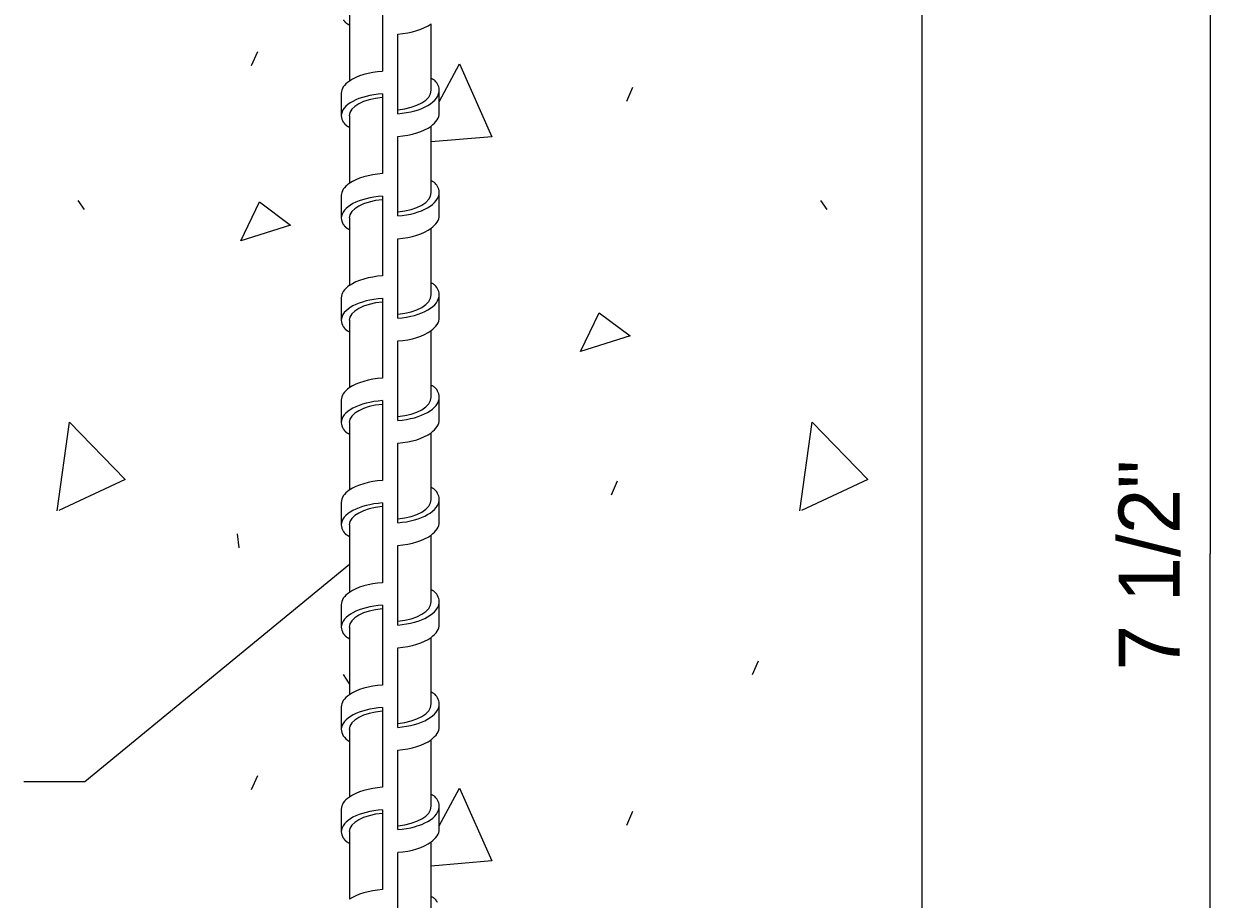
# Model space of a CAD drawing. Extents: x 99988 to 100172, y 99995 to 100047.
# Drawn here: x 100013.574 to 100014.934, y 100005.845 to 100006.848 of the extents above; entities that cross this region are included whole.
import ezdxf

# ---------------------------------------------------------------- set-up
doc = ezdxf.new("R2010")
doc.units = 0
for name, color, linetype in [('Level 10', 7, 'Continuous'), ('Level 15', 7, 'Continuous'), ('Level 2', 7, 'Continuous'), ('Level 20', 7, 'Continuous'), ('Level 3', 7, 'Continuous')]:
    doc.layers.add(name, color=color, linetype=linetype)

msp = doc.modelspace()

# ---------------------------------------------------------------- linework, layer by layer
at = {"layer": 'Level 10'}
for p, q in [((100013.9475, 100006.8595), (100013.9475, 100006.8463)), ((100013.9475, 100006.8463), (100013.9475, 100006.782)), ((100014.0412, 100006.7851), (100014.0412, 100006.8477)), ((100014.0412, 100006.7714), (100014.0412, 100006.7851)), ((100013.9382, 100006.768), (100013.9382, 100006.7423)), ((100014.0505, 100006.7454), (100014.0505, 100006.7714)), ((100013.9475, 100006.7423), (100013.9475, 100006.7292)), ((100013.9475, 100006.7291), (100013.9475, 100006.6648)), ((100014.0412, 100006.6679), (100014.0412, 100006.7305)), ((100014.0412, 100006.6543), (100014.0412, 100006.6679)), ((100014.0505, 100006.6282), (100014.0505, 100006.6543)), ((100013.9382, 100006.6508), (100013.9382, 100006.6251)), ((100013.9475, 100006.6251), (100013.9475, 100006.6119)), ((100014.0412, 100006.5507), (100014.0412, 100006.6133)), ((100013.9475, 100006.6119), (100013.9475, 100006.5477)), ((100014.0412, 100006.5371), (100014.0412, 100006.5507)), ((100013.9382, 100006.5337), (100013.9382, 100006.5079)), ((100014.0505, 100006.511), (100014.0505, 100006.5371)), ((100013.9475, 100006.5079), (100013.9475, 100006.4948)), ((100013.9475, 100006.4948), (100013.9475, 100006.4305)), ((100014.0412, 100006.4335), (100014.0412, 100006.4961)), ((100014.0412, 100006.4199), (100014.0412, 100006.4335)), ((100013.9382, 100006.4165), (100013.9382, 100006.3907)), ((100014.0505, 100006.3939), (100014.0505, 100006.4199)), ((100013.9475, 100006.3907), (100013.9475, 100006.3773)), ((100013.9475, 100006.3773), (100013.9475, 100006.3133)), ((100014.0412, 100006.3163), (100014.0412, 100006.3789)), ((100014.0412, 100006.3027), (100014.0412, 100006.3163)), ((100014.0505, 100006.2767), (100014.0505, 100006.303)), ((100013.9382, 100006.2993), (100013.9382, 100006.2735)), ((100013.9475, 100006.2735), (100013.9475, 100006.2603)), ((100013.9475, 100006.2603), (100013.9475, 100006.1961)), ((100014.0412, 100006.1991), (100014.0412, 100006.2617)), ((100013.9475, 100006.1961), (100013.9475, 100006.1961)), ((100014.0412, 100006.1855), (100014.0412, 100006.1991)), ((100013.9382, 100006.1821), (100013.9382, 100006.1564)), ((100014.0505, 100006.1595), (100014.0505, 100006.1855)), ((100013.9475, 100006.1564), (100013.9475, 100006.1432)), ((100013.9475, 100006.1432), (100013.9475, 100006.0789)), ((100014.0412, 100006.0819), (100014.0412, 100006.1446)), ((100014.0412, 100006.0683), (100014.0412, 100006.0819)), ((100013.9382, 100006.0649), (100013.9382, 100006.0392)), ((100014.0505, 100006.0423), (100014.0505, 100006.0683)), ((100013.9475, 100006.0392), (100013.9475, 100006.0251)), ((100013.9475, 100006.0251), (100013.9475, 100005.9617)), ((100014.0412, 100005.9648), (100014.0412, 100006.0274)), ((100014.0412, 100005.9511), (100014.0412, 100005.9648)), ((100013.9382, 100005.9477), (100013.9382, 100005.922)), ((100014.0505, 100005.9251), (100014.0505, 100005.9511)), ((100013.9475, 100005.922), (100013.9475, 100005.9087)), ((100013.9475, 100005.9087), (100013.9475, 100005.8445)), ((100014.0412, 100005.8476), (100014.0412, 100005.9102)), ((100014.0412, 100005.8339), (100014.0412, 100005.8476))]:
    msp.add_line(p, q, dxfattribs=at)
for centre, major_axis, ratio, start_param, end_param in [((100013.9943, 100006.8626), (-0.0561, 0), 0.483341, 1.726906, 2.559242), ((100013.9943, 100006.768), (-0.0561, 0), 0.453331, 4.868499, 5.700713), ((100013.9943, 100006.768), (-0.0561, 0), 0.453331, 5.700747, 6.28324), ((100013.9943, 100006.7714), (-0.0561, 0), 0.483341, 3.170728, 3.398624), ((100013.9943, 100006.7423), (-0.0561, 0), 0.453331, 4.868499, 6.291084), ((100013.9943, 100006.7423), (-0.0469, 0), 0.453331, 4.899667, 6.283186), ((100013.9943, 100006.7714), (-0.0561, 0), 0.483341, 1.726906, 3.170728), ((100013.9943, 100006.7714), (0.0469, 0), 0.483341, 4.899667, 6.283186), ((100013.9943, 100006.7423), (-0.0561, 0), 0.453331, 0.007899, 0.291099), ((100013.9943, 100006.7454), (-0.0561, 0), 0.483341, 2.559062, 3.141593), ((100013.9943, 100006.7454), (-0.0561, 0), 0.483341, 1.726906, 2.559062), ((100013.9943, 100006.6508), (-0.0561, 0), 0.453331, 4.868499, 5.701215), ((100013.9943, 100006.6508), (-0.0561, 0), 0.453331, 5.701416, 6.28324), ((100013.9943, 100006.6543), (-0.0561, 0), 0.483341, 1.726906, 3.154379), ((100013.9943, 100006.6543), (0.0469, 0), 0.483341, 4.899667, 6.283186), ((100013.9943, 100006.6543), (-0.0561, 0), 0.483341, 3.157463, 3.398624), ((100013.9943, 100006.6543), (-0.0561, 0), 0.483341, 3.1559612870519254, 3.1559613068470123), ((100013.9943, 100006.6251), (-0.0561, 0), 0.453331, 4.868499, 6.285718), ((100013.9943, 100006.6251), (-0.0469, 0), 0.453331, 4.899667, 6.283186), ((100013.9943, 100006.6282), (-0.0561, 0), 0.483341, 2.559277, 3.141593), ((100013.9943, 100006.6251), (-0.0561, 0), 0.453331, 0.002533, 0.291099), ((100013.9943, 100006.6282), (-0.0561, 0), 0.483341, 1.726906, 2.559239), ((100013.9943, 100006.5337), (-0.0561, 0), 0.453331, 5.700807, 6.28324), ((100013.9943, 100006.5337), (-0.0561, 0), 0.453331, 4.868499, 5.700732), ((100013.9943, 100006.5079), (-0.0561, 0), 0.453331, 4.868499, 6.286829), ((100013.9943, 100006.5371), (-0.0561, 0), 0.483341, 1.726906, 3.164039), ((100013.9943, 100006.5371), (0.0469, 0), 0.483341, 4.899667, 6.283186), ((100013.9943, 100006.5371), (-0.0561, 0), 0.483341, 3.164109, 3.398624), ((100013.9943, 100006.5079), (-0.0469, 0), 0.453331, 4.899667, 6.283186), ((100013.9943, 100006.5079), (-0.0561, 0), 0.453331, 0.003942, 0.291099), ((100013.9943, 100006.511), (-0.0561, 0), 0.483341, 2.559128, 3.141593), ((100013.9943, 100006.511), (-0.0561, 0), 0.483341, 1.726906, 2.55906), ((100013.9943, 100006.4165), (-0.0561, 0), 0.453331, 4.868499, 5.70104), ((100013.9943, 100006.4165), (-0.0561, 0), 0.453331, 5.70104, 6.28324), ((100013.9943, 100006.4199), (-0.0561, 0), 0.483341, 3.148125, 3.398624), ((100013.9943, 100006.3907), (-0.0561, 0), 0.453331, 4.868499, 6.287652), ((100013.9943, 100006.3907), (-0.0469, 0), 0.453331, 4.899667, 6.283186), ((100013.9943, 100006.4199), (-0.0561, 0), 0.483341, 1.726906, 3.145553), ((100013.9943, 100006.4199), (0.0469, 0), 0.483341, 4.899667, 6.283186), ((100013.9943, 100006.4199), (-0.0561, 0), 0.483341, 3.14727, 3.148125), ((100013.9943, 100006.3907), (-0.0561, 0), 0.453331, 0.004522, 0.291099), ((100013.9943, 100006.3939), (-0.0561, 0), 0.483341, 2.559329, 3.141593), ((100013.9943, 100006.3939), (-0.0561, 0), 0.483341, 1.726906, 2.559329), ((100013.9943, 100006.2993), (-0.0561, 0), 0.453331, 4.868499, 5.700838), ((100013.9943, 100006.2993), (-0.0561, 0), 0.453331, 5.700838, 6.28324), ((100013.9943, 100006.3027), (-0.0561, 0), 0.483341, 1.726906, 3.154112), ((100013.9943, 100006.3027), (0.0469, 0), 0.483341, 4.899667, 6.283186), ((100013.9943, 100006.3027), (-0.0561, 0), 0.483341, 3.154112, 3.398624), ((100013.9943, 100006.2735), (-0.0561, 0), 0.453331, 4.868499, 6.287148), ((100013.9943, 100006.2735), (-0.0469, 0), 0.453331, 4.899667, 6.283186), ((100013.9943, 100006.2735), (-0.0561, 0), 0.453331, 0.003963, 0.291099), ((100013.9943, 100006.2767), (-0.0561, 0), 0.483341, 2.559264, 3.141593), ((100013.9943, 100006.2767), (-0.0561, 0), 0.483341, 1.726906, 2.559243), ((100013.9943, 100006.1821), (-0.0561, 0), 0.453331, 4.868499, 5.699987), ((100013.9943, 100006.1821), (-0.0561, 0), 0.453331, 5.699987, 6.28324), ((100013.9943, 100006.1855), (-0.0561, 0), 0.483341, 3.156067, 3.398624), ((100013.9943, 100006.1564), (-0.0561, 0), 0.453331, 4.868499, 6.285215), ((100013.9943, 100006.1855), (-0.0561, 0), 0.483341, 1.726906, 3.154373), ((100013.9943, 100006.1855), (0.0469, 0), 0.483341, 4.899667, 6.283186), ((100013.9943, 100006.1855), (-0.0561, 0), 0.483341, 3.155233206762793, 3.1552332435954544), ((100013.9943, 100006.1564), (-0.0469, 0), 0.453331, 4.899667, 6.283186), ((100013.9943, 100006.1564), (-0.0561, 0), 0.453331, 0.002031, 0.291099), ((100013.9943, 100006.1595), (-0.0561, 0), 0.483341, 2.559645, 3.141593), ((100013.9943, 100006.1595), (-0.0561, 0), 0.483341, 1.726906, 2.559645), ((100013.9943, 100006.0649), (-0.0561, 0), 0.453331, 4.868499, 5.700435), ((100013.9943, 100006.0649), (-0.0561, 0), 0.453331, 5.700435, 6.28324), ((100013.9943, 100006.0683), (-0.0561, 0), 0.483341, 3.15176, 3.398624), ((100013.9943, 100006.0392), (-0.0561, 0), 0.453331, 4.868499, 6.279323), ((100013.9943, 100006.0392), (-0.0469, 0), 0.453331, 4.899667, 6.283186), ((100013.9943, 100006.0683), (-0.0561, 0), 0.483341, 1.726906, 3.15176), ((100013.9943, 100006.0683), (0.0469, 0), 0.483341, 4.899667, 6.283186), ((100013.9943, 100006.0392), (-0.0561, 0), 0.453331, 6.279328, 6.86573), ((100013.9943, 100006.0423), (-0.0561, 0), 0.483341, 2.559545, 3.141593), ((100013.9943, 100006.0423), (-0.0561, 0), 0.483341, 1.726906, 2.559545), ((100013.9943, 100005.9477), (-0.0561, 0), 0.453331, 5.700036, 6.28324), ((100013.9943, 100005.9477), (-0.0561, 0), 0.453331, 4.868499, 5.700036), ((100013.9943, 100005.9511), (-0.0561, 0), 0.483341, 1.726906, 3.163128), ((100013.9943, 100005.9511), (0.0469, 0), 0.483341, 4.899667, 6.283186), ((100013.9943, 100005.9511), (-0.0561, 0), 0.483341, 3.166399, 3.398624), ((100013.9943, 100005.922), (-0.0561, 0), 0.453331, 4.868499, 6.28541), ((100013.9943, 100005.922), (-0.0469, 0), 0.453331, 4.899667, 6.283186), ((100013.9943, 100005.922), (-0.0561, 0), 0.453331, 0.002225, 0.291099), ((100013.9943, 100005.9251), (-0.0561, 0), 0.483341, 2.558021, 3.141593), ((100013.9943, 100005.9251), (-0.0561, 0), 0.483341, 1.726906, 2.55759), ((100013.9943, 100005.8305), (-0.0561, 0), 0.453331, 4.868499, 5.700533)]:
    msp.add_ellipse(centre, major_axis=major_axis, ratio=ratio, start_param=start_param, end_param=end_param, dxfattribs=at)
for points, degree in [([(100013.9856, 100006.8846), (100013.9856, 100006.8817), (100013.9856, 100006.8788), (100013.9856, 100006.876), (100013.9856, 100006.8635), (100013.9856, 100006.851), (100013.9856, 100006.8385), (100013.9856, 100006.8234), (100013.9856, 100006.8083), (100013.9856, 100006.7932)], 3), ([(100013.9406, 100006.8522), (100013.9421, 100006.8499), (100013.9444, 100006.8479), (100013.9475, 100006.8463)], 2), ([(100014.0031, 100006.7446), (100014.0031, 100006.7475), (100014.0031, 100006.7504), (100014.0031, 100006.7533), (100014.0031, 100006.7658), (100014.0031, 100006.7783), (100014.0031, 100006.7908), (100014.0031, 100006.8058), (100014.0031, 100006.8208), (100014.0031, 100006.8358)], 3), ([(100014.0486, 100006.7783), (100014.0472, 100006.7809), (100014.0451, 100006.7831), (100014.0418, 100006.7848), (100014.0415, 100006.7849), (100014.0412, 100006.785)], 3), ([(100013.9856, 100006.7674), (100013.9856, 100006.7645), (100013.9856, 100006.7617), (100013.9856, 100006.7588), (100013.9856, 100006.7463), (100013.9856, 100006.7338), (100013.9856, 100006.7213), (100013.9856, 100006.7062), (100013.9856, 100006.6911), (100013.9856, 100006.676)], 3), ([(100013.9406, 100006.735), (100013.9421, 100006.7327), (100013.9444, 100006.7307), (100013.9475, 100006.7292)], 2), ([(100014.0031, 100006.6275), (100014.0031, 100006.6303), (100014.0031, 100006.6332), (100014.0031, 100006.6361), (100014.0031, 100006.6486), (100014.0031, 100006.6611), (100014.0031, 100006.6736), (100014.0031, 100006.6886), (100014.0031, 100006.7036), (100014.0031, 100006.7186)], 3), ([(100014.0486, 100006.6612), (100014.0472, 100006.6637), (100014.0451, 100006.6659), (100014.0418, 100006.6676), (100014.0415, 100006.6677), (100014.0412, 100006.6679)], 3), ([(100013.9856, 100006.6502), (100013.9856, 100006.6474), (100013.9856, 100006.6445), (100013.9856, 100006.6416), (100013.9856, 100006.6291), (100013.9856, 100006.6166), (100013.9856, 100006.6041), (100013.9856, 100006.589), (100013.9856, 100006.5739), (100013.9856, 100006.5588)], 3), ([(100013.9406, 100006.6178), (100013.9421, 100006.6155), (100013.9444, 100006.6135), (100013.9475, 100006.612)], 2), ([(100014.0031, 100006.5103), (100014.0031, 100006.5132), (100014.0031, 100006.516), (100014.0031, 100006.5189), (100014.0031, 100006.5314), (100014.0031, 100006.5439), (100014.0031, 100006.5564), (100014.0031, 100006.5714), (100014.0031, 100006.5864), (100014.0031, 100006.6014)], 3), ([(100014.0486, 100006.544), (100014.0472, 100006.5465), (100014.0451, 100006.5487), (100014.0418, 100006.5504), (100014.0415, 100006.5505), (100014.0412, 100006.5507)], 3), ([(100013.9856, 100006.5331), (100013.9856, 100006.5302), (100013.9856, 100006.5273), (100013.9856, 100006.5244), (100013.9856, 100006.5119), (100013.9856, 100006.4994), (100013.9856, 100006.4869), (100013.9856, 100006.4718), (100013.9856, 100006.4567), (100013.9856, 100006.4416)], 3), ([(100013.9406, 100006.5006), (100013.9421, 100006.4983), (100013.9444, 100006.4963), (100013.9475, 100006.4948)], 2), ([(100014.0031, 100006.3931), (100014.0031, 100006.396), (100014.0031, 100006.3989), (100014.0031, 100006.4017), (100014.0031, 100006.4142), (100014.0031, 100006.4267), (100014.0031, 100006.4392), (100014.0031, 100006.4542), (100014.0031, 100006.4692), (100014.0031, 100006.4842)], 3), ([(100014.0486, 100006.4268), (100014.0472, 100006.4293), (100014.0451, 100006.4315), (100014.0418, 100006.4332), (100014.0415, 100006.4334), (100014.0412, 100006.4335)], 3), ([(100013.9856, 100006.4159), (100013.9856, 100006.413), (100013.9856, 100006.4101), (100013.9856, 100006.4072), (100013.9856, 100006.3947), (100013.9856, 100006.3822), (100013.9856, 100006.3697), (100013.9856, 100006.3546), (100013.9856, 100006.3395), (100013.9856, 100006.3244)], 3), ([(100013.9406, 100006.3834), (100013.9421, 100006.3811), (100013.9444, 100006.3791), (100013.9475, 100006.3776)], 2), ([(100014.0031, 100006.2759), (100014.0031, 100006.2788), (100014.0031, 100006.2817), (100014.0031, 100006.2845), (100014.0031, 100006.297), (100014.0031, 100006.3095), (100014.0031, 100006.322), (100014.0031, 100006.337), (100014.0031, 100006.3521), (100014.0031, 100006.3671)], 3), ([(100014.0486, 100006.3096), (100014.0472, 100006.3121), (100014.0451, 100006.3143), (100014.0418, 100006.316), (100014.0415, 100006.3162), (100014.0412, 100006.3163)], 3), ([(100013.9856, 100006.2987), (100013.9856, 100006.2958), (100013.9856, 100006.2929), (100013.9856, 100006.29), (100013.9856, 100006.2775), (100013.9856, 100006.265), (100013.9856, 100006.2525), (100013.9856, 100006.2374), (100013.9856, 100006.2223), (100013.9856, 100006.2072)], 3), ([(100013.9406, 100006.2662), (100013.9421, 100006.2639), (100013.9444, 100006.2619), (100013.9475, 100006.2604)], 2), ([(100014.0031, 100006.1587), (100014.0031, 100006.1616), (100014.0031, 100006.1645), (100014.0031, 100006.1674), (100014.0031, 100006.1799), (100014.0031, 100006.1924), (100014.0031, 100006.2049), (100014.0031, 100006.2199), (100014.0031, 100006.2349), (100014.0031, 100006.2499)], 3), ([(100014.0486, 100006.1924), (100014.0472, 100006.1949), (100014.0451, 100006.1971), (100014.0418, 100006.1988), (100014.0415, 100006.199), (100014.0412, 100006.1991)], 3), ([(100013.9856, 100006.1815), (100013.9856, 100006.1786), (100013.9856, 100006.1757), (100013.9856, 100006.1728), (100013.9856, 100006.1603), (100013.9856, 100006.1478), (100013.9856, 100006.1353), (100013.9856, 100006.1202), (100013.9856, 100006.1051), (100013.9856, 100006.09)], 3), ([(100013.9406, 100006.1491), (100013.9421, 100006.1468), (100013.9444, 100006.1448), (100013.9475, 100006.1432)], 2), ([(100014.0031, 100006.0415), (100014.0031, 100006.0444), (100014.0031, 100006.0473), (100014.0031, 100006.0502), (100014.0031, 100006.0627), (100014.0031, 100006.0752), (100014.0031, 100006.0877), (100014.0031, 100006.1027), (100014.0031, 100006.1177), (100014.0031, 100006.1327)], 3), ([(100014.0486, 100006.0752), (100014.0472, 100006.0778), (100014.0451, 100006.0799), (100014.0418, 100006.0817), (100014.0415, 100006.0818), (100014.0412, 100006.0819)], 3), ([(100013.9856, 100006.0643), (100013.9856, 100006.0614), (100013.9856, 100006.0585), (100013.9856, 100006.0556), (100013.9856, 100006.0431), (100013.9856, 100006.0306), (100013.9856, 100006.0181), (100013.9856, 100006.003), (100013.9856, 100005.9879), (100013.9856, 100005.9729)], 3), ([(100014.0031, 100005.9243), (100014.0031, 100005.9272), (100014.0031, 100005.9301), (100014.0031, 100005.933), (100014.0031, 100005.9455), (100014.0031, 100005.958), (100014.0031, 100005.9705), (100014.0031, 100005.9855), (100014.0031, 100006.0005), (100014.0031, 100006.0155)], 3), ([(100014.0486, 100005.958), (100014.0472, 100005.9606), (100014.0451, 100005.9627), (100014.0418, 100005.9645), (100014.0415, 100005.9646), (100014.0412, 100005.9647)], 3), ([(100013.9856, 100005.9471), (100013.9856, 100005.9442), (100013.9856, 100005.9413), (100013.9856, 100005.9385), (100013.9856, 100005.926), (100013.9856, 100005.9135), (100013.9856, 100005.901), (100013.9856, 100005.8859), (100013.9856, 100005.8708), (100013.9856, 100005.8557)], 3), ([(100013.9406, 100005.9147), (100013.9421, 100005.9124), (100013.9444, 100005.9104), (100013.9475, 100005.9088)], 2), ([(100014.0031, 100005.8071), (100014.0031, 100005.81), (100014.0031, 100005.8129), (100014.0031, 100005.8158), (100014.0031, 100005.8283), (100014.0031, 100005.8408), (100014.0031, 100005.8533), (100014.0031, 100005.8683), (100014.0031, 100005.8833), (100014.0031, 100005.8983)], 3), ([(100014.0486, 100005.8408), (100014.0472, 100005.8434), (100014.0451, 100005.8456), (100014.0418, 100005.8473), (100014.0415, 100005.8474), (100014.0412, 100005.8475)], 3)]:
    msp.add_open_spline(points, degree=degree, dxfattribs=at)
at = {"layer": 'Level 15'}
for p in [(100014.9337, 100006.966), (100014.9337, 100005.5145)]:
    msp.add_line(p, (100014.9337, 100006.2402), dxfattribs=at)
msp.add_lwpolyline([(100013.9475, 100006.2282), (100013.6444, 100005.9791), (100013.5744, 100005.9791)], dxfattribs=at)
at = {"layer": 'Level 2'}
msp.add_line((100014.6037, 100005.2589), (100014.6037, 100006.9464), dxfattribs=at)
at = {"layer": 'Level 3'}
for p, q in [((100013.8355, 100006.7998), (100013.8426, 100006.8158)), ((100014.2653, 100006.759), (100014.2724, 100006.775)), ((100013.6366, 100006.6453), (100013.6437, 100006.6347)), ((100014.4873, 100006.6453), (100014.4944, 100006.6347)), ((100014.2476, 100006.3079), (100014.2547, 100006.3239)), ((100013.8191, 100006.2633), (100013.8208, 100006.2473)), ((100014.4092, 100006.1019), (100014.4163, 100006.1178)), ((100013.9403, 100006.1019), (100013.9474, 100006.0912)), ((100013.9474, 100006.0978), (100013.9475, 100006.0977)), ((100013.8355, 100005.9702), (100013.8426, 100005.9862)), ((100014.2653, 100005.9294), (100014.2724, 100005.9453))]:
    msp.add_line(p, q, dxfattribs=at)
for points in [[(100014.0505, 100006.7581), (100014.0735, 100006.8016), (100014.1108, 100006.7181), (100014.0412, 100006.7122)], [(100013.8231, 100006.5991), (100013.8444, 100006.6436), (100013.8799, 100006.6169), (100013.8231, 100006.5991)], [(100014.2124, 100006.4722), (100014.2337, 100006.5166), (100014.2692, 100006.49), (100014.2124, 100006.4722)], [(100013.6129, 100006.2895), (100013.627, 100006.391), (100013.6906, 100006.3253), (100013.6145, 100006.2901)], [(100014.4636, 100006.2895), (100014.4777, 100006.391), (100014.5413, 100006.3253), (100014.4653, 100006.2901)], [(100014.0505, 100005.9285), (100014.0735, 100005.972), (100014.1108, 100005.8885), (100014.0412, 100005.8826)]]:
    msp.add_lwpolyline(points, dxfattribs=at)

# ---------------------------------------------------------------- texts
at = {"layer": 'Level 20'}
msp.add_text('7 1/2"', height=0.07, rotation=90, dxfattribs=at).set_placement((100014.8987, 100006.1067))

doc.saveas('drawing.dxf')
